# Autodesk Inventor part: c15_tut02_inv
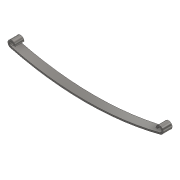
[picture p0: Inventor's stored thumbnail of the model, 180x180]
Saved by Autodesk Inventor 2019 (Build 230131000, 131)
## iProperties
Created: 2017-05
Part Number: c15_tut02_inv
Material: Steel, Mild
Document SubType Name: Modeling
Designer: CADCIM 00
Mass: 5.6491 g
Surface Area: 16.9114 cm^2
Volume: 0.71963 cm^3
Density: 7.85 g/cm^3
Appearance: Semi-Polished
Author: CADCIM 00
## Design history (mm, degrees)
sketch "Sketch1"
  geometry: L1 (0, 0)-(0, 18.068); L2 (48.5, 8.9)-(47.5, 8.9); L3 (-48.5, 8.9)-(-47.5, 8.9); A1 r 200 centre (0, 201) between (-50.378, 7.449) and (50.378, 7.449); A2 r 201 centre (0, 201) between (-50.63, 6.481) and (50.63, 6.481); A3 r 1.5 centre (50, 8.9) between (50.378, 7.449) and (48.5, 8.9); A4 r 2.5 centre (50, 8.9) between (50.63, 6.481) and (47.5, 8.9); A5 r 1.5 centre (-50, 8.9) between (-48.5, 8.9) and (-50.378, 7.449); A6 r 2.5 centre (-50, 8.9) between (-47.5, 8.9) and (-50.63, 6.481); 5 further points
  constraints: 13 point on circle, 6 centre point, 6 end point, 6 symmetric about line, 5 horizontal alignment, 3 coincident, 2 tangent, 1 horizontal, 1 midpoint, 1 vertical, 2 other
  dimensions: "d0" = 200 radius of A1; "d1" = 1 radial gap between concentric circles of A2 A1; "d2" = 2.5 radius of A4; "d3" = 50 distance from line of L1 A3.centre
extrude "Extrusion1" new body sketch "Sketch1" distance "d4" = 6; taper "d5" = 0 deg
body "Solid1"
